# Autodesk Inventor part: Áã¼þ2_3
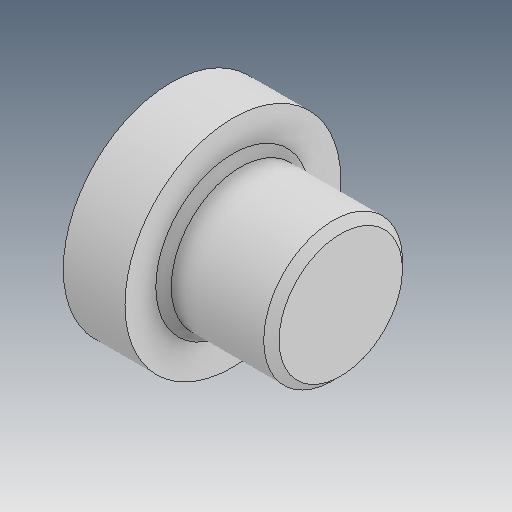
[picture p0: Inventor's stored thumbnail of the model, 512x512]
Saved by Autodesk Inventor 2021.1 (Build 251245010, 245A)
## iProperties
Created: 2019-04
Part Number: Áã¼þ2_3
Material: Ogólny
Document SubType Name: Modeling
Designer: user
Density: 1 g/cm^3
Appearance: Domyślna
Author: user
Revision Number: ÈÎºÎ
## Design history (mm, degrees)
feature "ÊäÈë1"
node "Bryła1"
